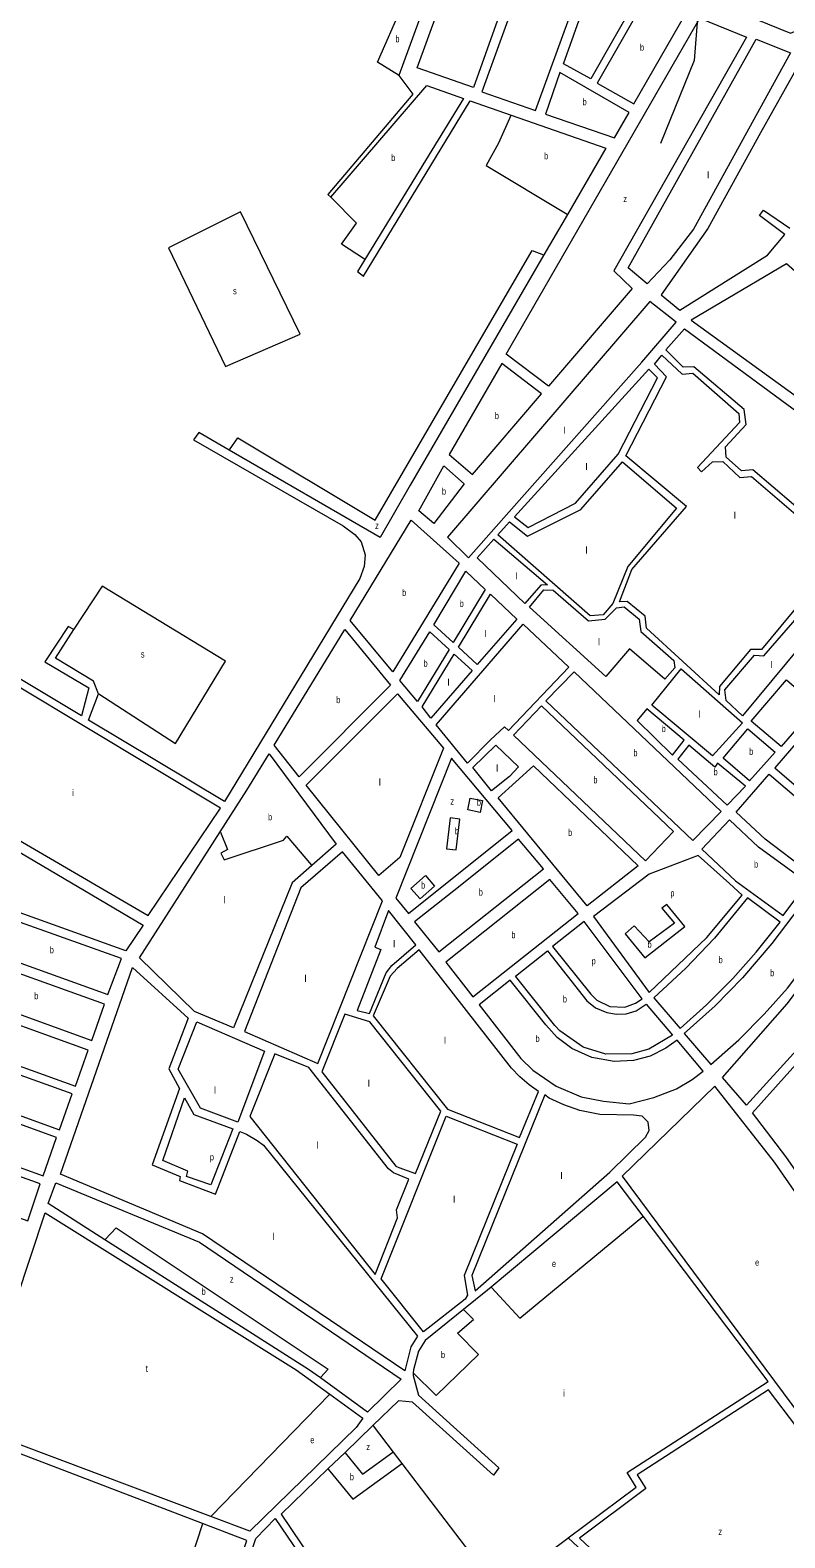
# Model space of a CAD drawing. Extents: x 639657 to 671642, y 222838 to 252123.
# Drawn here: x 650477 to 651595, y 228746 to 230977 of the extents above; entities that cross this region are included whole.
import ezdxf

# ---------------------------------------------------------------- set-up
doc = ezdxf.new("R2010")
doc.units = 0
doc.header["$LTSCALE"] = 4
for name, color, linetype, lineweight in [('1', 7, 'Continuous', 13), ('21', 7, 'Continuous', 13), ('57', 7, 'Continuous', 35)]:
    doc.layers.add(name, color=color, linetype=linetype, lineweight=lineweight)
doc.layers.add('7', color=7, linetype='Continuous')

msp = doc.modelspace()

# ---------------------------------------------------------------- linework, layer by layer
at = {"layer": '1'}
for p, q in [((651186.5, 230263.78), (651383.47, 230485.93)), ((651393.457, 230475.812), (651194.789, 230257.219)), ((651570.21, 228977.69), (651385.28, 229222.052)), ((650889.88, 228995.31), (650588.222, 229187.101)), ((651154.671, 229112.622), (651119.347, 229084.087))]:
    msp.add_line(p, q, dxfattribs=at)
for points in [[(651133.8, 230892.43), (651050.8, 230921.74), (651174.91, 231262.71), (651255.86, 231234.79)], [(651146.32, 230886.17), (651225.79, 230858.49), (651350.65, 231201.34), (651270.77, 231229.53)], [(651307.706, 230905.464), (651267.39, 230927.51), (651310.79, 231049.59), (651378, 231028.6)], [(651316.97, 230898.8), (651371.39, 230868.27), (651459.93, 231021.58), (651389.36, 231025.36)], [(651182.62, 230497.65), (651469.14, 230995.07), (651538.28, 230967.06), (651341.8, 230621.31), (651368.86, 230595.04), (651244.95, 230450.53)], [(651363.27, 230625.6), (651552.64, 230964.1), (651603.6, 230943.66), (651459.71, 230682.85), (651424.86, 230637.37), (651391.36, 230602.03)], [(651261.85, 230914.63), (651240.47, 230853.11), (651342.81, 230817.74), (651364.69, 230855.45)], [(651642.31, 230413.41), (651716.35, 230527.1), (651597.33, 230631.49), (651456.48, 230547.94)], [(651234.58, 230439.03), (651175.89, 230483.74), (651098.01, 230349.3), (651132.74, 230319.66)], [(651052.91, 230265.82), (651090.13, 230332.41), (651120.39, 230305.85), (651075.4, 230247.37)], [(651306.85, 230110.7), (651170.18, 230230.64), (651187.29, 230249.7), (651213.9, 230228.69), (651293.04, 230268.16), (651354.65, 230338.24), (651434.6, 230269.91), (651362.41, 230183.56), (651340.23, 230128.63), (651326.17, 230111.88)], [(651041.79, 230252.04), (651112.62, 230188.35), (651014.45, 230027.76), (650951.34, 230103.46)], [(651210, 230129.04), (651139.23, 230196.5), (651163.96, 230223.98), (651243.5, 230156.28), (651233.52, 230155.81)], [(651151.27, 230149.44), (651103.97, 230071.14), (651075.35, 230097.27), (651122.9, 230176.5)], [(651329.79, 230020.58), (651216.87, 230123.16), (651238.29, 230148.94), (651252.07, 230148.3), (651304.18, 230103.32), (651328.89, 230105.51), (651345.65, 230122.39), (651357.14, 230124.11), (651379.33, 230105.51), (651381.8, 230087.43), (651430.59, 230044.32), (651432.28, 230033.57), (651417.37, 230016.84), (651364.83, 230061.61)], [(651139.23, 230038.44), (651111.62, 230064.05), (651159, 230142.38), (651197.96, 230105.51)], [(651532.34, 229962.57), (651508.44, 229985.13), (651506.44, 230001.18), (651549.92, 230052.26), (651564.12, 230051.6), (651616.87, 230112.08), (651640.97, 230093.44)], [(650838.83, 229919.12), (650943.39, 230090.38), (651011.09, 230007.78), (650876.04, 229872.38)], [(651051.28, 229983.92), (651025.01, 230014.95), (651069.33, 230086.68), (651097.75, 230060.84)], [(651058.16, 229975.68), (651105.44, 230053.84), (651131.97, 230029.71), (651070.79, 229959.19)], [(650652.41, 229667.06), (650759.47, 229825.93), (650458.53, 230006.48), (650407.94, 230020.41), (650320.98, 229860.15)], [(651282.85, 230027.8), (651500.55, 229820.91), (651458.84, 229777.87), (651241.3, 229984.55)], [(651487.89, 229903.24), (651397.96, 229978.533), (651441.77, 230032.16), (651532.18, 229952.18)], [(651641.83, 229977.17), (651589.79, 229917.11), (651545.16, 229954.73), (651597.49, 230015.84)], [(650994.056, 229726.134), (650886.13, 229859.81), (651021.26, 229994.98), (651089.54, 229914.79), (651024.75, 229752.99)], [(651234.66, 229977.54), (651430.2, 229791.32), (651388.71, 229748.12), (651193.06, 229934.13)], [(651376.49, 229955.54), (651428.767, 229904.354), (651446.04, 229926.41), (651390.56, 229972.71)], [(651542.9, 229866.25), (651503.62, 229900.16), (651540.31, 229943.35), (651580.71, 229909)], [(651580.17, 229885.74), (651745.85, 229743.63), (651783.09, 229786.96), (651617.35, 229928.74)], [(651167.245, 229919.187), (651200.55, 229887.14), (651187.28, 229872.63), (651160.81, 229851.51), (651132.975, 229886.003)], [(651436.46, 229898.34), (651509.66, 229830.16), (651536.88, 229858.4), (651495.57, 229892.3), (651491.62, 229886.64), (651452.92, 229919.08)], [(651018.98, 229692.92), (651037.54, 229669.82), (651191.24, 229792.65), (651101.63, 229899.8)], [(651302.19, 229681.21), (651170.48, 229841.28), (651222.85, 229888.48), (651377.77, 229740.37)], [(651693.24, 229683.37), (651565.93, 229780.04), (651522.85, 229820.23), (651572, 229876.47), (651737.85, 229734.71)], [(650415.56, 229695.42), (650424.88, 229691.88), (650451.93, 229766.97), (650644.64, 229652.88), (650619.02, 229614.94), (650272.78, 229738.91), (650269.16, 229756.64), (650274.33, 229772.99), (650314.55, 229848.56), (650370.09, 229815.59), (650341.56, 229729.62), (650352.79, 229726.1), (650379.97, 229809.87), (650442.06, 229772.91)], [(651592.79, 229667.08), (651628.74, 229715.35), (651556.06, 229768.02), (651513.29, 229808.77), (651472.17, 229765.19), (651522.23, 229718.34)], [(651104.65, 229703.82), (651046.59, 229657.85), (651082.85, 229613.14), (651237.6, 229735.97), (651200.64, 229780.14)], [(650878.44, 229707.82), (650794.69, 229495.46), (650903.45, 229448.27), (650999.41, 229688.62), (650939.83, 229761.14)], [(651311.522, 229665.855), (651394.247, 229552.982), (651479.34, 229634.368), (651531.897, 229696.973), (651513.126, 229714.502), (651466.826, 229755.821), (651394.247, 229728.275)], [(651247.19, 229720.19), (651093.02, 229598.13), (651133.12, 229546.56), (651289, 229670.04)], [(651599.06, 229559.75), (651684.15, 229671.77), (651638.25, 229707.73), (651575.75, 229625.55), (651532.38, 229575.03), (651491.91, 229533.38), (651446.2, 229492.48), (651485.49, 229446.75), (651526.77, 229483.16), (651564.63, 229521.16)], [(651539.68, 229693.36), (651490.76, 229633.39), (651448.61, 229589.07), (651401.09, 229545.3), (651439.89, 229499.77), (651479.15, 229534.69), (651517.91, 229573.94), (651552.64, 229612.64), (651587.96, 229657.41)], [(650419.71, 229672.24), (650401.42, 229618.57), (650592.69, 229550.07), (650612.6, 229603.38)], [(651008.2, 229674.44), (650987.67, 229620.29), (650996.71, 229616.65), (650961.9, 229526.52), (650979.76, 229522), (651004.57, 229582.33), (651012.85, 229592.86), (651048.53, 229623.76)], [(651297.94, 229658.14), (651251.24, 229621.14), (651307.61, 229550.67), (651316.91, 229541.61), (651336.05, 229532.32), (651358.3, 229531.36), (651373.86, 229537.46), (651383.94, 229543.73)], [(651598.36, 229536.25), (651694.84, 229663.37), (651840.96, 229532.93), (651712.1, 229397.41), (651717.12, 229258.59), (651671.45, 229202.93), (651596.66, 229310.64), (651547.22, 229374.89), (651628.4, 229465.1), (651617.62, 229473.56), (651538.31, 229386.33), (651502.89, 229427.6)], [(651053.79, 229616.48), (651021, 229588.42), (651010.5, 229577.28), (650985.63, 229518.55), (651095.61, 229380.55), (651202.37, 229338.44), (651230.25, 229406.49), (651216.59, 229416.31), (651202.66, 229428.23), (651190.27, 229441.09)], [(651243.37, 229614.87), (651302.1, 229541.05), (651314.82, 229530.4), (651331.34, 229523.32), (651345.77, 229521.02), (651359.88, 229521.67), (651374.78, 229526.15), (651389.79, 229535.68), (651428.86, 229489.94), (651393.56, 229469.06), (651368.51, 229462.18), (651330.07, 229461.92), (651296.35, 229472.43), (651261.68, 229496.66), (651254.71, 229504.15), (651196.2, 229577.38)], [(650395.89, 229604.44), (650376.62, 229551.57), (650568.76, 229482.06), (650587.53, 229536.11)], [(650797.9, 229343.69), (650813.48, 229334.18), (650823.13, 229327.06), (651050.86, 229044.74), (651041.35, 229028.83), (651032.21, 228993.14), (650732.54, 229195.82), (650522.17, 229284.23), (650628.93, 229590.25), (650711.39, 229514.95), (650682.97, 229440.13), (650698.68, 229411.21), (650657.92, 229297.98), (650699.72, 229280.95), (650698.68, 229274.79), (650751.87, 229254.69), (650787.891, 229347.39)], [(651142.27, 229534.71), (651203.9, 229455.26), (651221.85, 229438.11), (651256.3, 229414.51), (651293.66, 229398.7), (651326.33, 229392.25), (651364.79, 229388.6), (651401.07, 229397.79), (651434.59, 229410.75), (651458.06, 229424.52), (651474.3, 229436.92), (651435.39, 229482.44), (651418.77, 229470.52), (651395.47, 229459.17), (651371.11, 229452.73), (651342.58, 229451.05), (651309.33, 229456.89), (651279.59, 229470.43), (651257.95, 229486.6), (651241, 229505.33), (651188.43, 229571.32)], [(650371.58, 229536.91), (650352.37, 229483.5), (650544.56, 229414.53), (650563.34, 229467.62)], [(650943.58, 229521.32), (650909.55, 229435.5), (651018.96, 229296.36), (651023.2, 229294.08), (651047.96, 229285.17), (651085.46, 229377.67), (650980.38, 229509.75)], [(650824.57, 229466.57), (650784.94, 229361.43), (650729.89, 229382.2), (650696.56, 229439.69), (650724.43, 229509.89)], [(650348.1, 229471.97), (650332.81, 229417.85), (650520.75, 229349.91), (650539.48, 229403.15)], [(650802.96, 229369.73), (650988.59, 229135.92), (651021.38, 229219.46), (651019.86, 229231.3), (651038.35, 229277.09), (651015.78, 229286.04), (651007.93, 229292.44), (650890.15, 229442.21), (650839.55, 229462.21)], [(650329.78, 229406.12), (650315.43, 229346.8), (650496.82, 229281.85), (650516.69, 229338.38)], [(650706.181, 229397.438), (650719.69, 229372.59), (650777.37, 229351.27), (650744.98, 229268.64), (650708.86, 229280.95), (650711.11, 229288.74), (650673.8, 229304.33)], [(651136.303, 229111.585), (651336.06, 229287.09), (651388.9, 229339.19), (651394.13, 229349.17), (651392.61, 229361.06), (651383.84, 229369.91), (651370.87, 229371.64), (651321.07, 229372.77), (651291.58, 229378.69), (651268.01, 229386.82), (651246.23, 229396.97), (651239.43, 229401.56), (651131.78, 229134.26)], [(651060.01, 229050.88), (650997.15, 229129.35), (651093.51, 229370.04), (651198.49, 229328.49), (651120.29, 229134.3), (651125.09, 229105.48), (651121.81, 229099.1)], [(650312.84, 229334.27), (650298.51, 229277.08), (650474.08, 229215.15), (650492.28, 229269.93)]]:
    msp.add_lwpolyline(points, close=True, dxfattribs=at)
for points in [[(651551.311, 230993.942), (651603.46, 230972.83), (651615.15, 230977.9), (651634.57, 231009.59), (651646.47, 231035.14), (651663.37, 231078.67), (651670.035, 231108.216)], [(651028.077, 231012.432), (651053.19, 230991.23), (651023.64, 230910.24)], [(651747.16, 230860), (651680.05, 230918.47), (651631.23, 230929.5), (651614.02, 230923.18), (651559.11, 230825.42), (651481.09, 230683.57), (651411.97, 230585.59), (651439.76, 230562.85), (651569.59, 230644.15), (651594.952, 230674.98), (651557.627, 230702.836), (651563.352, 230710.856), (651602.384, 230684.014)], [(651023.64, 230910.24), (651044.29, 230882.53), (650918.35, 230734.02), (650922.96, 230729.99)], [(650922.96, 230729.99), (651064.88, 230895.32), (651119.04, 230876.14), (650973.186, 230637.989)], [(650973.186, 230637.989), (650962.31, 230620.23), (650970.92, 230613.35), (651129.28, 230872.54), (651189.655, 230851.508)], [(651189.655, 230851.508), (651330.14, 230802.57), (651273.111, 230704.477), (651238.352, 230644.688)], [(651238.352, 230644.688), (651040.17, 230303.8), (650995.96, 230226.43), (650772.395, 230355.85)], [(651395.18, 230575.87), (651095.536, 230226.73), (651126.8, 230196.15), (651186.5, 230263.78)], [(651383.47, 230485.93), (651434.06, 230545.02), (651395.18, 230575.87)], [(651637.97, 230249.65), (651547.54, 230326.44), (651530.97, 230325.22), (651508.38, 230345.32), (651507.14, 230360.61), (651537.6, 230393.86), (651534.77, 230415.97), (651460.46, 230479.13), (651444.54, 230478.54), (651418.86, 230504.41), (651446.72, 230535.15), (651678.72, 230364.7)], [(651634.45, 230149.99), (651560.66, 230060.78), (651544.11, 230060.63), (651498.24, 230005.77), (651498.05, 229993.89), (651390.15, 230092.39), (651388.1, 230109.82), (651361.51, 230131.89), (651350.38, 230131.39), (651368.64, 230179.31), (651449.28, 230272.43), (651359.79, 230347.49), (651419.71, 230464.4), (651401.94, 230482.83), (651413, 230496.44), (651442.89, 230468.38), (651459.04, 230469.81), (651526.82, 230410.16), (651527.88, 230396.77), (651465.55, 230330.25), (651471.85, 230323.59), (651488.11, 230338.43), (651503.19, 230339.03), (651528.48, 230315.29), (651545.48, 230316.71), (651632.34, 230242.53)], [(651348.116, 230349.906), (651406.31, 230462.79), (651393.457, 230475.812)], [(650772.395, 230355.85), (650727.05, 230382.1), (650719.33, 230370.84), (650941.17, 230243.73), (650958.27, 230231.03), (650967.41, 230220.31), (650973.44, 230200.73), (650972.25, 230183.38), (650965.78, 230166.05), (650765.46, 229835.64), (650564.07, 229956.29), (650578.46, 229995.27)], [(651194.789, 230257.219), (651214.94, 230241.27), (651284.92, 230277.41), (651348.116, 230349.906)], [(650541.88, 230090.54), (650533.77, 230095.02), (650499.41, 230042.38), (650564.29, 230003.8), (650553.55, 229962.39), (650331.65, 230095.24), (650334.56, 230141.45), (650306.56, 230139.8), (650299.84, 230097.74), (650399.07, 230037.63), (650400.93, 230032.04), (650310.51, 229863.67), (650001.738, 229918.761)], [(650578.46, 229995.27), (650571.09, 230014.1), (650514.96, 230047.67), (650541.88, 230090.54)], [(651159.28, 229926.85), (651125.324, 229892.564), (651078.78, 229949.4), (651207.42, 230098.45)], [(651207.42, 230098.45), (651275.41, 230034.6), (651185.67, 229940.72), (651180, 229946.17), (651159.28, 229926.85)], [(650758.952, 229790.997), (650798.487, 229852.731), (650831.2, 229906.25), (650930.67, 229772.8), (650894.549, 229741.057), (650865.33, 229715.38)], [(650865.33, 229715.38), (650778.51, 229500.88), (650720.67, 229525.04), (650639.47, 229604.43), (650758.952, 229790.997)], [(651929.955, 228797.451), (651579.72, 229302.12), (651491.38, 229414.76), (651354.16, 229281.3), (651751.026, 228747.718)], [(650588.222, 229187.101), (650503.95, 229240.68), (650515.43, 229271.72), (650728.04, 229183.51), (651026.67, 228980.83), (650977.26, 228932.26), (650907.198, 228982.814), (650889.88, 228995.31)], [(651385.28, 229222.052), (651346.642, 229273.107), (651160.195, 229117.24), (651154.671, 229112.622)], [(650745.255, 228777.74), (650402.16, 228906.48), (650413.18, 228967.78), (650499.63, 229226.97)], [(650499.63, 229226.97), (650871.59, 228994.58), (650921.092, 228958.781)], [(651119.347, 229084.087), (651062.63, 229038.27), (651052.59, 229022.47), (651045.1, 228994.78), (651044.875, 228990.47)], [(651044.875, 228990.47), (651044.65, 228986.16), (651052.44, 228957.45), (651171.56, 228849.54), (651163.77, 228838.88), (651043.6, 228946.78), (651022.77, 228948.83), (650985.01, 228912.344), (650943.713, 228872.441), (650918.488, 228848.067)], [(651274.26, 228746.14), (651374.71, 228820.98), (651361.81, 228842.75), (651570.21, 228977.69)], [(651738.877, 228744.342), (651571.067, 228964.95), (651376.52, 228839.59), (651389.39, 228818.91), (651290.98, 228745.67), (651501.927, 228548.753)], [(650921.092, 228958.781), (650970.03, 228923.39), (650960.09, 228909.61), (650802.66, 228756.2), (650745.255, 228777.74)], [(650735.14, 228553.1), (650798.3, 228742.19), (650732.89, 228767.239), (650445.117, 228877.441)], [(650918.488, 228848.067), (650849.11, 228781.03), (651167.73, 228309.31), (651503.94, 228532.46), (651274.26, 228746.14)], [(650747.88, 228552.88), (650811.78, 228744.9), (650840.49, 228774.64), (650884.155, 228710.013), (651023.381, 228503.951), (651038.832, 228481.082), (651108.019, 228378.681)]]:
    msp.add_lwpolyline(points, dxfattribs=at)
at = {"layer": '21'}
for points in [[(651023.64, 230910.24), (651023.14, 230910.554), (650991.973, 230930.146), (651027.858, 231011.932), (651028.077, 231012.432)], [(651189.655, 230851.508), (651189.43, 230851.008), (651171.027, 230810.091), (651152.568, 230776.845), (651272.611, 230704.777), (651273.111, 230704.477)], [(650973.186, 230637.989), (650972.686, 230638.313), (650938.442, 230660.484), (650960.593, 230691.883), (650923.454, 230729.49), (650922.96, 230729.99)], [(650772.395, 230355.85), (650772.745, 230356.35), (650785.23, 230374.198), (650988.281, 230252.296), (651220.867, 230651.249), (651237.852, 230644.876), (651238.352, 230644.688)], [(650578.46, 229995.27), (650578.96, 229994.949), (650692.934, 229921.682), (650766.771, 230043.584), (650584.025, 230154.405), (650542.21, 230091.04), (650541.88, 230090.54)], [(650758.952, 229790.997), (650759.158, 229790.497), (650769.82, 229764.585), (650759.81, 229759.577), (650764.815, 229749.56), (650852.41, 229778.358), (650857.415, 229784.619), (650894.123, 229741.557), (650894.549, 229741.057)], [(651160.195, 229117.24), (651160.653, 229116.74), (651202.419, 229071.151), (651384.78, 229221.639), (651385.28, 229222.052)], [(650588.222, 229187.101), (650588.683, 229187.601), (650604.641, 229204.898), (650918.732, 228995.798), (650907.642, 228983.314), (650907.198, 228982.814)], [(651044.875, 228990.47), (651078.742, 228956.636), (651141.504, 229017.587), (651110.123, 229048.987), (651134.12, 229069.304), (651119.847, 229083.587), (651119.347, 229084.087)], [(650745.255, 228777.74), (650745.741, 228778.24), (650920.606, 228958.281), (650921.092, 228958.781)], [(650985.01, 228912.344), (650985.391, 228911.844), (651014.946, 228873.104), (651027.978, 228856.023)], [(650918.488, 228848.067), (650918.897, 228847.567), (650955.065, 228803.334), (651027.478, 228855.662), (651027.978, 228856.023)], [(650943.713, 228872.441), (650944.119, 228871.941), (650969.833, 228840.274), (651014.446, 228872.74), (651014.946, 228873.104)], [(651027.978, 228856.023), (651171.039, 228668.502), (651273.76, 228745.764), (651274.26, 228746.14)], [(650732.89, 228767.239), (650732.726, 228766.739), (650560.036, 228239.073), (650625.53, 228217.228), (650626.03, 228217.061)]]:
    msp.add_lwpolyline(points, dxfattribs=at)
for points in [[(650682.454, 230655.24), (650766.771, 230479.477), (650877.526, 230527.499), (650788.922, 230708.506)], [(651128.96, 229840.963), (651147.494, 229837.254), (651143.977, 229819.678), (651125.443, 229823.387)], [(651093.922, 229765.838), (651108.235, 229764.047), (651113.944, 229809.661), (651099.631, 229811.452)], [(651041.365, 229706.989), (651062.793, 229726.047), (651076.403, 229710.745), (651054.975, 229691.687)], [(651358.685, 229640.156), (651387.991, 229604.318), (651446.804, 229650.645), (651420.526, 229683.2), (651413.018, 229678.191), (651431.788, 229655.654), (651394.247, 229628.108), (651371.723, 229651.897)]]:
    msp.add_lwpolyline(points, close=True, dxfattribs=at)
at = {"layer": '57', "lineweight": 13}
msp.add_lwpolyline([(651773.011, 234750.407), (651803.088, 233802.52), (651824.392, 233344.878), (651834.418, 233046.469), (651800.582, 232947.418), (651773.012, 232904.788), (651712.859, 232864.666), (651627.642, 232834.575), (651569.995, 232794.452), (651547.438, 232724.239), (651549.945, 232561.242), (651539.919, 232378.185), (651519.868, 232014.578), (651468.488, 231032.839), (651460.969, 230932.533), (651410.841, 230809.659)], dxfattribs=at)

# ---------------------------------------------------------------- texts
at = {"layer": '7'}
for s, width, p in [('b', 0.75, (651018.342, 230959.39)), ('b', 0.75, (651380.593, 230946.815)), ('b', 0.75, (651295.525, 230866.185)), ('b', 0.75, (651012.163, 230783.582)), ('b', 0.75, (651238.457, 230786.125)), ('z', 0.8, (651355.892, 230722.8)), ('s', 0.8, (650777.905, 230586.4)), ('b', 0.75, (651165.548, 230401.7)), ('b', 0.75, (651087.238, 230289.89)), ('z', 0.8, (650988.339, 230239.163)), ('b', 0.75, (651028.263, 230139.9)), ('b', 0.75, (651113.539, 230123.82)), ('s', 0.8, (650641.307, 230048.921)), ('b', 0.75, (651059.952, 230035.3)), ('b', 0.75, (650930.8, 229981.38)), ('b', 0.75, (651412.688, 229938.532)), ('b', 0.75, (651370.827, 229902.835)), ('b', 0.75, (651542.279, 229904.8)), ('b', 0.75, (651489.521, 229874.62)), ('b', 0.75, (651311.583, 229862.83)), ('z', 0.8, (651099.789, 229831.138)), ('b', 0.75, (651138.971, 229829.694)), ('b', 0.75, (650829.69, 229807.969)), ('b', 0.75, (651106.436, 229787.123)), ('b', 0.75, (651274.083, 229784.845)), ('b', 0.75, (651549.446, 229737.925)), ('b', 0.75, (651056.382, 229706.989)), ('b', 0.75, (651141.815, 229696.64)), ('p', 0.75, (651425.562, 229695.354)), ('b', 0.75, (651190.126, 229633.375)), ('b', 0.75, (650506.473, 229611.155)), ('b', 0.75, (651391.745, 229619.343)), ('p', 0.75, (651308.969, 229594.75)), ('b', 0.75, (651496.976, 229596.565)), ('b', 0.75, (651573.311, 229577.24)), ('b', 0.75, (650483.562, 229543.25)), ('b', 0.75, (651266.31, 229538.395)), ('b', 0.75, (651225.788, 229479.96)), ('p', 0.75, (650743.547, 229304.671)), ('e', 0.75, (651250.174, 229146.94)), ('e', 0.75, (651551.06, 229148.787)), ('z', 0.8, (650773.221, 229123.771)), ('b', 0.75, (650731.312, 229105.747)), ('b', 0.75, (651085.887, 229012.108)), ('e', 0.75, (650892.309, 228886.122)), ('z', 0.8, (650975.369, 228876.027)), ('b', 0.75, (650950.81, 228831.424)), ('z', 0.8, (651496.694, 228750.302))]:
    msp.add_text(s, height=10, dxfattribs=dict(at, width=width)).set_placement(p)
for s, p in [('l', (651480.037, 230757.997)), ('l', (651267.062, 230379.915)), ('l', (651299.851, 230326.327)), ('l', (651519.54, 230254.148)), ('l', (651299.851, 230202.748)), ('l', (651196.018, 230164.471)), ('l', (651150.114, 230079.168)), ('l', (651318.432, 230067.138)), ('l', (651574.189, 230033.236)), ('l', (651095.465, 230006.988)), ('l', (651163.229, 229982.929)), ('l', (651467.077, 229959.963)), ('l', (651167.601, 229880.128)), ('l', (650993.818, 229859.349)), ('i', (650539.474, 229843.735)), ('l', (650763.569, 229685.307)), ('l', (651015.091, 229620.199)), ('l', (650883.699, 229568.863)), ('l', (651090.173, 229477.46)), ('l', (650749.804, 229403.586)), ('l', (650977.551, 229413.603)), ('l', (650901.218, 229322.2)), ('l', (651262.86, 229277.124)), ('l', (651103.938, 229242.066)), ('l', (650836.147, 229186.974)), ('t', (650648.426, 228991.585)), ('i', (651266.463, 228955.174))]:
    msp.add_text(s, height=10, dxfattribs=at).set_placement(p)

doc.saveas('drawing.dxf')
